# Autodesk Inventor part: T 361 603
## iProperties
Company: Mayer & Müller AG Schaltgeräte
Created: 2006-03
Part Number: T 361 603
Material: 1.0112.00
Document SubType Name: Modeling
Designer: I.Baliuc
Description: Grundplatte
Density: 7.84 g/cm^3
Rohabmessung: Fl. 120 x 10
HalbzeugNorm: DIN 174
Author: T.Messerschmitt
Keywords: 380117
Revision Number: 361603
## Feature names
1. Extrusion2
2. Bohrung1 [Hole]
